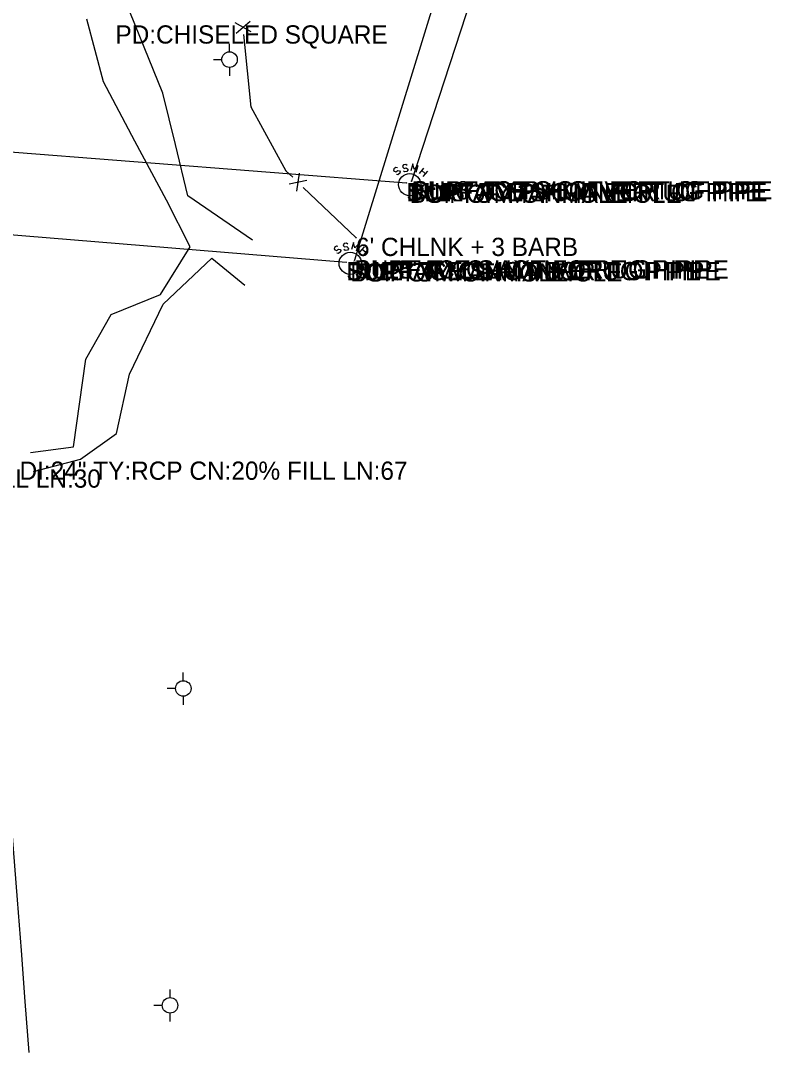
# Model space of a CAD drawing. Extents: x 929765 to 934279, y 1533086 to 1541189.
# Drawn here: x 932063 to 932268.9, y 1537035.9 to 1537318.7 of the extents above; entities that cross this region are included whole.
import ezdxf

# ---------------------------------------------------------------- set-up
doc = ezdxf.new("R2010")
doc.units = 0
for name, color, linetype in [('S_CROSS_DRAIN_ANNOT', 7, 'Continuous'), ('S_DITCHLINE', 7, 'Continuous'), ('S_FENCE', 7, 'Continuous'), ('S_FENCE_ANNOT', 7, 'Continuous'), ('S_MANHOLE_ANNOT', 7, 'Continuous'), ('S_MSC_PT_SYM', 7, 'Continuous'), ('S_PRIMARY_CTL_ANNOT', 7, 'Continuous'), ('S_SANITARY_SEWER', 7, 'Continuous'), ('S_SANITARY_SEWER_ANNOT', 7, 'Continuous'), ('S_SHOULDER', 7, 'Continuous'), ('S_SURVEY_TEXT_ANNOT', 7, 'Continuous'), ('S_UTILITY_POLE', 7, 'Continuous'), ('S_UTL_PT_SYM', 7, 'Continuous')]:
    doc.layers.add(name, color=color, linetype=linetype)

msp = doc.modelspace()

# ---------------------------------------------------------------- linework, layer by layer
at = {"layer": 'S_DITCHLINE'}
for points in [[(932126.62, 1537258.44), (932108.91, 1537270.62), (932105.45, 1537284.68), (932101.98, 1537298.75), (932094.32, 1537317.71), (932086.66, 1537336.67), (932081.51, 1537352.24), (932076.37, 1537367.8), (932068.43, 1537383.73), (932067.92, 1537400.37), (932067.42, 1537417), (932077.7, 1537427.87), (932087.98, 1537438.73), (932101.66, 1537459.25), (932108.63, 1537471.21), (932115.61, 1537483.17), (932113.54, 1537495.88)], [(932065.68, 1537200.24), (932077.5, 1537201.85), (932080.91, 1537225.83), (932087.81, 1537238.09), (932101.36, 1537243.6), (932109.52, 1537256.64), (932102.98, 1537269.42), (932094.38, 1537285.63), (932085.78, 1537301.84), (932081.18, 1537319.05)], [(932066.53, 1537195.1), (932079.46, 1537198.49), (932089.29, 1537205.46), (932092.83, 1537221.77), (932102.13, 1537240.92), (932115.44, 1537253.57), (932124.48, 1537246.12)]]:
    msp.add_lwpolyline(points, dxfattribs=at)
at = {"layer": 'S_FENCE'}
for p, q in [((932126.25, 1537315.62), (932121.88, 1537318.06)), ((932126.25, 1537315.62), (932121.88, 1537318.06)), ((932122.17, 1537315.21), (932125.96, 1537318.47)), ((932122.17, 1537315.21), (932125.96, 1537318.47)), ((932141.56, 1537274.83), (932136.65, 1537273.85)), ((932141.56, 1537274.83), (932136.65, 1537273.85)), ((932138.73, 1537271.87), (932139.48, 1537276.81)), ((932138.73, 1537271.87), (932139.48, 1537276.81))]:
    msp.add_line(p, q, dxfattribs=at)
for points in [[(932126.26, 1537294.97), (932124.27, 1537314.85)], [(932126.26, 1537294.97), (932124.27, 1537314.85)], [(932135.87, 1537277.43), (932126.27, 1537294.96)], [(932135.87, 1537277.43), (932126.27, 1537294.96)], [(932137.66, 1537275.72), (932135.87, 1537277.43)], [(932137.66, 1537275.72), (932135.87, 1537277.43)], [(932155.01, 1537259.14), (932140.55, 1537272.96)], [(932155.01, 1537259.14), (932140.55, 1537272.96)]]:
    msp.add_lwpolyline(points, dxfattribs=at)
at = {"layer": 'S_MSC_PT_SYM'}
for points in [[(932126.26, 1537294.97), (932126.26, 1537295.02), (932126.26, 1537294.97), (932126.21, 1537294.97), (932126.26, 1537294.97), (932126.26, 1537294.92), (932126.26, 1537294.97), (932126.31, 1537294.97)], [(932135.87, 1537277.43), (932135.87, 1537277.48), (932135.87, 1537277.43), (932135.82, 1537277.43), (932135.87, 1537277.43), (932135.87, 1537277.38), (932135.87, 1537277.43), (932135.92, 1537277.43)], [(932168.84, 1537274.16), (932168.84, 1537274.21), (932168.84, 1537274.16), (932168.79, 1537274.16), (932168.84, 1537274.16), (932168.84, 1537274.11), (932168.84, 1537274.16), (932168.89, 1537274.16)], [(932170.26, 1537274.65), (932170.26, 1537274.7), (932170.26, 1537274.65), (932170.21, 1537274.65), (932170.26, 1537274.65), (932170.26, 1537274.6), (932170.26, 1537274.65), (932170.31, 1537274.65)], [(932155.01, 1537259.14), (932155.01, 1537259.19), (932155.01, 1537259.14), (932154.96, 1537259.14), (932155.01, 1537259.14), (932155.01, 1537259.09), (932155.01, 1537259.14), (932155.06, 1537259.14)], [(932152.35, 1537252.49), (932152.35, 1537252.54), (932152.35, 1537252.49), (932152.3, 1537252.49), (932152.35, 1537252.49), (932152.35, 1537252.44), (932152.35, 1537252.49), (932152.4, 1537252.49)], [(932154.58, 1537252.96), (932154.58, 1537253.01), (932154.58, 1537252.96), (932154.53, 1537252.96), (932154.58, 1537252.96), (932154.58, 1537252.91), (932154.58, 1537252.96), (932154.63, 1537252.96)]]:
    msp.add_lwpolyline(points, dxfattribs=at)
at = {"layer": 'S_SANITARY_SEWER'}
for p, q in [((932255.38, 1537536.13), (932170.26, 1537274.65)), ((932236.41, 1537518.54), (932154.58, 1537252.96)), ((931951.89, 1537291.15), (932168.84, 1537274.16)), ((932165.4, 1537278.01), (932165.32, 1537277.62)), ((932165.32, 1537277.62), (932165.52, 1537277.35)), ((932165.94, 1537278.4), (932165.4, 1537278.01)), ((932165.52, 1537277.35), (932165.94, 1537277.23)), ((932166.37, 1537278.32), (932165.94, 1537278.4)), ((932165.94, 1537277.23), (932166.49, 1537277.58)), ((932166.49, 1537277.58), (932166.95, 1537277.5)), ((932166.95, 1537277.5), (932167.11, 1537277.23)), ((932167.11, 1537277.23), (932167.03, 1537276.81)), ((932172.38, 1537276.77), (932173.62, 1537278.24)), ((932173.03, 1537277.54), (932174, 1537276.73)), ((932174.58, 1537277.43), (932173.34, 1537275.95)), ((932166.49, 1537276.42), (932166.1, 1537276.5)), ((932167.03, 1537276.81), (932166.49, 1537276.42)), ((931930.95, 1537270.6), (932152.35, 1537252.49)), ((932149.1, 1537256.46), (932149.02, 1537256.07)), ((932149.02, 1537256.07), (932149.21, 1537255.8)), ((932149.64, 1537256.85), (932149.1, 1537256.46)), ((932149.21, 1537255.8), (932149.64, 1537255.68)), ((932150.06, 1537256.77), (932149.64, 1537256.85)), ((932149.64, 1537255.68), (932150.18, 1537256.03)), ((932150.18, 1537254.87), (932149.79, 1537254.95)), ((932150.18, 1537256.03), (932150.65, 1537255.95)), ((932150.72, 1537255.26), (932150.18, 1537254.87)), ((932150.65, 1537255.95), (932150.8, 1537255.68)), ((932150.8, 1537255.68), (932150.72, 1537255.26)), ((932156.07, 1537255.22), (932157.31, 1537256.69)), ((932156.73, 1537255.99), (932157.7, 1537255.18)), ((932158.28, 1537255.88), (932157.04, 1537254.4))]:
    msp.add_line(p, q, dxfattribs=at)
for points in [[(932169.04, 1537278.94), (932168.69, 1537279.21), (932168.04, 1537279.13), (932167.8, 1537278.78), (932167.84, 1537278.47), (932168.19, 1537278.16), (932168.81, 1537278.28), (932169.2, 1537277.97), (932169.24, 1537277.66), (932168.97, 1537277.27), (932168.35, 1537277.19), (932168, 1537277.47)], [(932171.48, 1537277.08), (932172.03, 1537278.94), (932170.98, 1537277.93), (932170.59, 1537279.36), (932170.05, 1537277.5)], [(932152.74, 1537257.39), (932152.39, 1537257.66), (932151.73, 1537257.58), (932151.5, 1537257.23), (932151.54, 1537256.92), (932151.89, 1537256.61), (932152.51, 1537256.73), (932152.89, 1537256.42), (932152.93, 1537256.11), (932152.66, 1537255.72), (932152.04, 1537255.64), (932151.69, 1537255.92)], [(932155.18, 1537255.53), (932155.72, 1537257.39), (932154.68, 1537256.38), (932154.29, 1537257.81), (932153.75, 1537255.95)]]:
    msp.add_lwpolyline(points, dxfattribs=at)
for centre in [(932169.73, 1537273.7), (932153.42, 1537252.15)]:
    msp.add_circle(centre, 3.05, dxfattribs=at)
at = {"layer": 'S_SHOULDER'}
msp.add_lwpolyline([(932065.34, 1537035.86), (932064.27, 1537049.8), (932063.21, 1537063.74), (932062.14, 1537077.68), (932061.08, 1537091.63), (932059.66, 1537108.77), (932058.23, 1537125.91), (932056.81, 1537143.06), (932055.39, 1537160.2), (932053.73, 1537179.84), (932052.07, 1537199.48), (932050.41, 1537219.11), (932048.75, 1537238.75), (932047.67, 1537252.72), (932046.6, 1537266.7), (932045.52, 1537280.67), (932044.45, 1537294.64), (932042.28, 1537319.47), (932040.11, 1537344.3), (932038.43, 1537365.02), (932036.75, 1537385.74), (932035.07, 1537406.47), (932033.39, 1537427.19)], dxfattribs=at)
at = {"layer": 'S_UTILITY_POLE'}
for p, q in [((932120.32, 1537310.08), (932120.32, 1537312.32)), ((932118.22, 1537307.95), (932115.9, 1537307.95)), ((932120.39, 1537303.53), (932120.39, 1537305.85)), ((932107.63, 1537137.71), (932107.63, 1537139.95)), ((932105.53, 1537135.58), (932103.21, 1537135.58)), ((932107.7, 1537131.16), (932107.7, 1537133.48)), ((932103.99, 1537050.85), (932103.99, 1537053.09)), ((932101.9, 1537048.71), (932099.57, 1537048.71)), ((932104.07, 1537044.3), (932104.07, 1537046.62))]:
    msp.add_line(p, q, dxfattribs=at)
for centre in [(932120.32, 1537307.97), (932107.63, 1537135.6), (932103.99, 1537048.74)]:
    msp.add_circle(centre, 2.13, dxfattribs=at)
at = {"layer": 'S_UTL_PT_SYM'}
for points in [[(932168.84, 1537274.16), (932168.84, 1537274.21), (932168.84, 1537274.16), (932168.79, 1537274.16), (932168.84, 1537274.16), (932168.84, 1537274.11), (932168.84, 1537274.16), (932168.89, 1537274.16)], [(932170.26, 1537274.65), (932170.26, 1537274.7), (932170.26, 1537274.65), (932170.21, 1537274.65), (932170.26, 1537274.65), (932170.26, 1537274.6), (932170.26, 1537274.65), (932170.31, 1537274.65)], [(932169.73, 1537273.7), (932169.73, 1537273.76), (932169.73, 1537273.7), (932169.68, 1537273.7), (932169.73, 1537273.7), (932169.73, 1537273.66), (932169.73, 1537273.7), (932169.78, 1537273.7)], [(932152.35, 1537252.49), (932152.35, 1537252.54), (932152.35, 1537252.49), (932152.3, 1537252.49), (932152.35, 1537252.49), (932152.35, 1537252.44), (932152.35, 1537252.49), (932152.4, 1537252.49)], [(932153.42, 1537252.15), (932153.42, 1537252.2), (932153.42, 1537252.15), (932153.37, 1537252.15), (932153.42, 1537252.15), (932153.42, 1537252.1), (932153.42, 1537252.15), (932153.47, 1537252.15)], [(932154.58, 1537252.96), (932154.58, 1537253.01), (932154.58, 1537252.96), (932154.53, 1537252.96), (932154.58, 1537252.96), (932154.58, 1537252.91), (932154.58, 1537252.96), (932154.63, 1537252.96)]]:
    msp.add_lwpolyline(points, dxfattribs=at)

# ---------------------------------------------------------------- texts
at = {"layer": 'S_CROSS_DRAIN_ANNOT'}
for s, p in [('DI:24" TY:RCP CN:20% FILL LN:67', (932062.71, 1537192.8)), ("DI:30' TY:CMP CN:30% FILL LN:30", (931978.95, 1537190.64))]:
    msp.add_text(s, height=5, dxfattribs=at).set_placement(p)
at = {"layer": 'S_FENCE_ANNOT'}
msp.add_text("6' CHLNK + 3 BARB", height=5, dxfattribs=at).set_placement((932155.01, 1537254.14))
at = {"layer": 'S_MANHOLE_ANNOT'}
for p in [(932169.73, 1537268.71), (932153.42, 1537247.15)]:
    msp.add_text('BOTTOM OF MANHOLE', height=5, dxfattribs=at).set_placement(p)
at = {"layer": 'S_PRIMARY_CTL_ANNOT'}
msp.add_text('PD:CHISELED SQUARE', height=5, dxfattribs=at).set_placement((932089.01, 1537312.36))
at = {"layer": 'S_SANITARY_SEWER_ANNOT'}
for s, p in [('DI:18" TY:PVC INVERT OF PIPE', (932168.84, 1537269.16)), ('DI:18" TY:PVC INVERT OF PIPE', (932170.26, 1537269.65)), ('TOP OF MANHOLE', (932169.73, 1537268.71)), ('DI:15" TY:CLAY INVERT OF PIPE', (932152.35, 1537247.49)), ('TOP OF MANHOLE', (932153.42, 1537247.15)), ('DI:15" TY:CLAY INVERT OF PIPE', (932154.58, 1537247.96))]:
    msp.add_text(s, height=5, dxfattribs=at).set_placement(p)
at = {"layer": 'S_SURVEY_TEXT_ANNOT'}
for p in [(932168.84, 1537269.16), (932170.26, 1537269.65), (932152.35, 1537247.49), (932154.58, 1537247.96)]:
    msp.add_text('SURFACE SHOT FOR UG PIPE', height=5, dxfattribs=at).set_placement(p)

doc.saveas('drawing.dxf')
